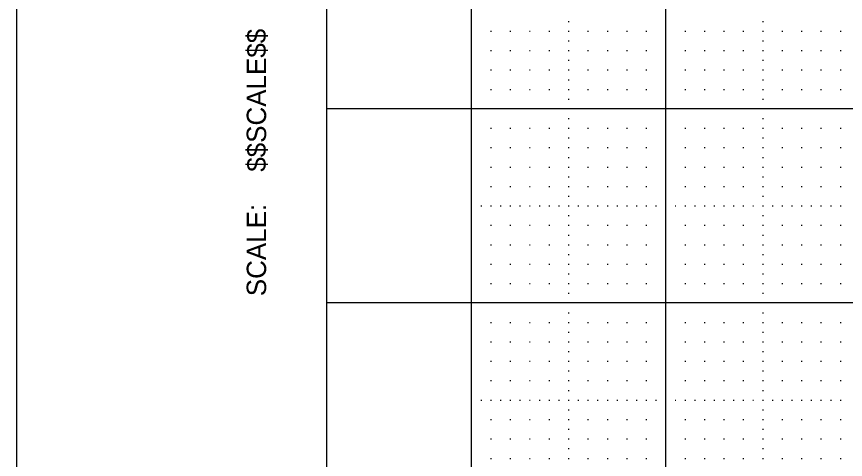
# Model space of a CAD drawing. Extents: x -1.6 to 32.7, y -1.7 to 21.9.
# Drawn here: x -1.598 to 2.67, y 2.487 to 4.768 of the extents above; entities that cross this region are included whole.
import ezdxf

# ---------------------------------------------------------------- set-up
doc = ezdxf.new("R2010")
doc.units = 0
for name, color, linetype in [('Level 1', 7, 'Continuous'), ('Level 5', 7, 'Continuous'), ('Level 63', 7, 'Continuous'), ('R_Border_Dark', 7, 'Continuous')]:
    doc.layers.add(name, color=color, linetype=linetype)

msp = doc.modelspace()

# ---------------------------------------------------------------- linework, layer by layer
at = {"layer": 'Level 1'}
msp.add_line((-0.001, -0.001), (-0.001, 20.545), dxfattribs=at)
msp.add_lwpolyline([(0.745, 10.272), (30.745, 10.272), (30.745, 0.293), (0.745, 0.293)], close=True, dxfattribs=at)
at = {"layer": 'Level 5'}
for p, q in [((1.2425, 4.743), (1.2475, 4.743)), ((2.2425, 4.743), (2.2475, 4.743)), ((0.8425, 4.693), (0.8475, 4.693)), ((0.9425, 4.693), (0.9475, 4.693)), ((1.0425, 4.693), (1.0475, 4.693)), ((1.1425, 4.693), (1.1475, 4.693)), ((1.2425, 4.693), (1.2475, 4.693)), ((1.3425, 4.693), (1.3475, 4.693)), ((1.4425, 4.693), (1.4475, 4.693)), ((1.5425, 4.693), (1.5475, 4.693)), ((1.6425, 4.693), (1.6475, 4.693)), ((1.8425, 4.693), (1.8475, 4.693)), ((1.9425, 4.693), (1.9475, 4.693)), ((2.0425, 4.693), (2.0475, 4.693)), ((2.1425, 4.693), (2.1475, 4.693)), ((2.2425, 4.693), (2.2475, 4.693)), ((2.3425, 4.693), (2.3475, 4.693)), ((2.4425, 4.693), (2.4475, 4.693)), ((2.5425, 4.693), (2.5475, 4.693)), ((2.6425, 4.693), (2.6475, 4.693)), ((1.2425, 4.643), (1.2475, 4.643)), ((2.2425, 4.643), (2.2475, 4.643)), ((0.8425, 4.593), (0.8475, 4.593)), ((0.9425, 4.593), (0.9475, 4.593)), ((1.0425, 4.593), (1.0475, 4.593)), ((1.1425, 4.593), (1.1475, 4.593)), ((1.2425, 4.593), (1.2475, 4.593)), ((1.3425, 4.593), (1.3475, 4.593)), ((1.4425, 4.593), (1.4475, 4.593)), ((1.5425, 4.593), (1.5475, 4.593)), ((1.6425, 4.593), (1.6475, 4.593)), ((1.8425, 4.593), (1.8475, 4.593)), ((1.9425, 4.593), (1.9475, 4.593)), ((2.0425, 4.593), (2.0475, 4.593)), ((2.1425, 4.593), (2.1475, 4.593)), ((2.2425, 4.593), (2.2475, 4.593)), ((2.3425, 4.593), (2.3475, 4.593)), ((2.4425, 4.593), (2.4475, 4.593)), ((2.5425, 4.593), (2.5475, 4.593)), ((2.6425, 4.593), (2.6475, 4.593)), ((1.2425, 4.543), (1.2475, 4.543)), ((2.2425, 4.543), (2.2475, 4.543)), ((0.8425, 4.493), (0.8475, 4.493)), ((0.9425, 4.493), (0.9475, 4.493)), ((1.0425, 4.493), (1.0475, 4.493)), ((1.1425, 4.493), (1.1475, 4.493)), ((1.2425, 4.493), (1.2475, 4.493)), ((1.3425, 4.493), (1.3475, 4.493)), ((1.4425, 4.493), (1.4475, 4.493)), ((1.5425, 4.493), (1.5475, 4.493)), ((1.6425, 4.493), (1.6475, 4.493)), ((1.8425, 4.493), (1.8475, 4.493)), ((1.9425, 4.493), (1.9475, 4.493)), ((2.0425, 4.493), (2.0475, 4.493)), ((2.1425, 4.493), (2.1475, 4.493)), ((2.2425, 4.493), (2.2475, 4.493)), ((2.3425, 4.493), (2.3475, 4.493)), ((2.4425, 4.493), (2.4475, 4.493)), ((2.5425, 4.493), (2.5475, 4.493)), ((2.6425, 4.493), (2.6475, 4.493)), ((1.2425, 4.443), (1.2475, 4.443)), ((2.2425, 4.443), (2.2475, 4.443)), ((0.8425, 4.393), (0.8475, 4.393)), ((0.9425, 4.393), (0.9475, 4.393)), ((1.0425, 4.393), (1.0475, 4.393)), ((1.1425, 4.393), (1.1475, 4.393)), ((1.2425, 4.393), (1.2475, 4.393)), ((1.3425, 4.393), (1.3475, 4.393)), ((1.4425, 4.393), (1.4475, 4.393)), ((1.5425, 4.393), (1.5475, 4.393)), ((1.6425, 4.393), (1.6475, 4.393)), ((1.8425, 4.393), (1.8475, 4.393)), ((1.9425, 4.393), (1.9475, 4.393)), ((2.0425, 4.393), (2.0475, 4.393)), ((2.1425, 4.393), (2.1475, 4.393)), ((2.2425, 4.393), (2.2475, 4.393)), ((2.3425, 4.393), (2.3475, 4.393)), ((2.4425, 4.393), (2.4475, 4.393)), ((2.5425, 4.393), (2.5475, 4.393)), ((2.6425, 4.393), (2.6475, 4.393)), ((1.2425, 4.343), (1.2475, 4.343)), ((2.2425, 4.343), (2.2475, 4.343)), ((1.2425, 4.243), (1.2475, 4.243)), ((2.2425, 4.243), (2.2475, 4.243)), ((0.8425, 4.193), (0.8475, 4.193)), ((0.9425, 4.193), (0.9475, 4.193)), ((1.0425, 4.193), (1.0475, 4.193)), ((1.1425, 4.193), (1.1475, 4.193)), ((1.2425, 4.193), (1.2475, 4.193)), ((1.3425, 4.193), (1.3475, 4.193)), ((1.4425, 4.193), (1.4475, 4.193)), ((1.5425, 4.193), (1.5475, 4.193)), ((1.6425, 4.193), (1.6475, 4.193)), ((1.8425, 4.193), (1.8475, 4.193)), ((1.9425, 4.193), (1.9475, 4.193)), ((2.0425, 4.193), (2.0475, 4.193)), ((2.1425, 4.193), (2.1475, 4.193)), ((2.2425, 4.193), (2.2475, 4.193)), ((2.3425, 4.193), (2.3475, 4.193)), ((2.4425, 4.193), (2.4475, 4.193)), ((2.5425, 4.193), (2.5475, 4.193)), ((2.6425, 4.193), (2.6475, 4.193)), ((1.2425, 4.143), (1.2475, 4.143)), ((2.2425, 4.143), (2.2475, 4.143)), ((0.8425, 4.093), (0.8475, 4.093)), ((0.9425, 4.093), (0.9475, 4.093)), ((1.0425, 4.093), (1.0475, 4.093)), ((1.1425, 4.093), (1.1475, 4.093)), ((1.2425, 4.093), (1.2475, 4.093)), ((1.3425, 4.093), (1.3475, 4.093)), ((1.4425, 4.093), (1.4475, 4.093)), ((1.5425, 4.093), (1.5475, 4.093)), ((1.6425, 4.093), (1.6475, 4.093)), ((1.8425, 4.093), (1.8475, 4.093)), ((1.9425, 4.093), (1.9475, 4.093)), ((2.0425, 4.093), (2.0475, 4.093)), ((2.1425, 4.093), (2.1475, 4.093)), ((2.2425, 4.093), (2.2475, 4.093)), ((2.3425, 4.093), (2.3475, 4.093)), ((2.4425, 4.093), (2.4475, 4.093)), ((2.5425, 4.093), (2.5475, 4.093)), ((2.6425, 4.093), (2.6475, 4.093)), ((1.2425, 4.043), (1.2475, 4.043)), ((2.2425, 4.043), (2.2475, 4.043)), ((0.8425, 3.993), (0.8475, 3.993)), ((0.9425, 3.993), (0.9475, 3.993)), ((1.0425, 3.993), (1.0475, 3.993)), ((1.1425, 3.993), (1.1475, 3.993)), ((1.2425, 3.993), (1.2475, 3.993)), ((1.3425, 3.993), (1.3475, 3.993)), ((1.4425, 3.993), (1.4475, 3.993)), ((1.5425, 3.993), (1.5475, 3.993)), ((1.6425, 3.993), (1.6475, 3.993)), ((1.8425, 3.993), (1.8475, 3.993)), ((1.9425, 3.993), (1.9475, 3.993)), ((2.0425, 3.993), (2.0475, 3.993)), ((2.1425, 3.993), (2.1475, 3.993)), ((2.2425, 3.993), (2.2475, 3.993)), ((2.3425, 3.993), (2.3475, 3.993)), ((2.4425, 3.993), (2.4475, 3.993)), ((2.5425, 3.993), (2.5475, 3.993)), ((2.6425, 3.993), (2.6475, 3.993)), ((1.2425, 3.943), (1.2475, 3.943)), ((2.2425, 3.943), (2.2475, 3.943)), ((0.8425, 3.893), (0.8475, 3.893)), ((0.9425, 3.893), (0.9475, 3.893)), ((1.0425, 3.893), (1.0475, 3.893)), ((1.1425, 3.893), (1.1475, 3.893)), ((1.2425, 3.893), (1.2475, 3.893)), ((1.3425, 3.893), (1.3475, 3.893)), ((1.4425, 3.893), (1.4475, 3.893)), ((1.5425, 3.893), (1.5475, 3.893)), ((1.6425, 3.893), (1.6475, 3.893)), ((1.8425, 3.893), (1.8475, 3.893)), ((1.9425, 3.893), (1.9475, 3.893)), ((2.0425, 3.893), (2.0475, 3.893)), ((2.1425, 3.893), (2.1475, 3.893)), ((2.2425, 3.893), (2.2475, 3.893)), ((2.3425, 3.893), (2.3475, 3.893)), ((2.4425, 3.893), (2.4475, 3.893)), ((2.5425, 3.893), (2.5475, 3.893)), ((2.6425, 3.893), (2.6475, 3.893)), ((1.2425, 3.843), (1.2475, 3.843)), ((2.2425, 3.843), (2.2475, 3.843)), ((0.7925, 3.793), (0.7975, 3.793)), ((0.8425, 3.793), (0.8475, 3.793)), ((0.8925, 3.793), (0.8975, 3.793)), ((0.9425, 3.793), (0.9475, 3.793)), ((0.9925, 3.793), (0.9975, 3.793)), ((1.0425, 3.793), (1.0475, 3.793)), ((1.0925, 3.793), (1.0975, 3.793)), ((1.1425, 3.793), (1.1475, 3.793)), ((1.1925, 3.793), (1.1975, 3.793)), ((1.2425, 3.793), (1.2475, 3.793)), ((1.2925, 3.793), (1.2975, 3.793)), ((1.3425, 3.793), (1.3475, 3.793)), ((1.3925, 3.793), (1.3975, 3.793)), ((1.4425, 3.793), (1.4475, 3.793)), ((1.4925, 3.793), (1.4975, 3.793)), ((1.5425, 3.793), (1.5475, 3.793)), ((1.5925, 3.793), (1.5975, 3.793)), ((1.6425, 3.793), (1.6475, 3.793)), ((1.6925, 3.793), (1.6975, 3.793)), ((1.7925, 3.793), (1.7975, 3.793)), ((1.8425, 3.793), (1.8475, 3.793)), ((1.8925, 3.793), (1.8975, 3.793)), ((1.9425, 3.793), (1.9475, 3.793)), ((1.9925, 3.793), (1.9975, 3.793)), ((2.0425, 3.793), (2.0475, 3.793)), ((2.0925, 3.793), (2.0975, 3.793)), ((2.1425, 3.793), (2.1475, 3.793)), ((2.1925, 3.793), (2.1975, 3.793)), ((2.2425, 3.793), (2.2475, 3.793)), ((2.2925, 3.793), (2.2975, 3.793)), ((2.3425, 3.793), (2.3475, 3.793)), ((2.3925, 3.793), (2.3975, 3.793)), ((2.4425, 3.793), (2.4475, 3.793)), ((2.4925, 3.793), (2.4975, 3.793)), ((2.5425, 3.793), (2.5475, 3.793)), ((2.5925, 3.793), (2.5975, 3.793)), ((2.6425, 3.793), (2.6475, 3.793)), ((1.2425, 3.743), (1.2475, 3.743)), ((2.2425, 3.743), (2.2475, 3.743)), ((0.8425, 3.693), (0.8475, 3.693)), ((0.9425, 3.693), (0.9475, 3.693)), ((1.0425, 3.693), (1.0475, 3.693)), ((1.1425, 3.693), (1.1475, 3.693)), ((1.2425, 3.693), (1.2475, 3.693)), ((1.3425, 3.693), (1.3475, 3.693)), ((1.4425, 3.693), (1.4475, 3.693)), ((1.5425, 3.693), (1.5475, 3.693)), ((1.6425, 3.693), (1.6475, 3.693)), ((1.8425, 3.693), (1.8475, 3.693)), ((1.9425, 3.693), (1.9475, 3.693)), ((2.0425, 3.693), (2.0475, 3.693)), ((2.1425, 3.693), (2.1475, 3.693)), ((2.2425, 3.693), (2.2475, 3.693)), ((2.3425, 3.693), (2.3475, 3.693)), ((2.4425, 3.693), (2.4475, 3.693)), ((2.5425, 3.693), (2.5475, 3.693)), ((2.6425, 3.693), (2.6475, 3.693)), ((1.2425, 3.643), (1.2475, 3.643)), ((2.2425, 3.643), (2.2475, 3.643)), ((0.8425, 3.593), (0.8475, 3.593)), ((0.9425, 3.593), (0.9475, 3.593)), ((1.0425, 3.593), (1.0475, 3.593)), ((1.1425, 3.593), (1.1475, 3.593)), ((1.2425, 3.593), (1.2475, 3.593)), ((1.3425, 3.593), (1.3475, 3.593)), ((1.4425, 3.593), (1.4475, 3.593)), ((1.5425, 3.593), (1.5475, 3.593)), ((1.6425, 3.593), (1.6475, 3.593)), ((1.8425, 3.593), (1.8475, 3.593)), ((1.9425, 3.593), (1.9475, 3.593)), ((2.0425, 3.593), (2.0475, 3.593)), ((2.1425, 3.593), (2.1475, 3.593)), ((2.2425, 3.593), (2.2475, 3.593)), ((2.3425, 3.593), (2.3475, 3.593)), ((2.4425, 3.593), (2.4475, 3.593)), ((2.5425, 3.593), (2.5475, 3.593)), ((2.6425, 3.593), (2.6475, 3.593)), ((1.2425, 3.543), (1.2475, 3.543)), ((2.2425, 3.543), (2.2475, 3.543)), ((0.8425, 3.493), (0.8475, 3.493)), ((0.9425, 3.493), (0.9475, 3.493)), ((1.0425, 3.493), (1.0475, 3.493)), ((1.1425, 3.493), (1.1475, 3.493)), ((1.2425, 3.493), (1.2475, 3.493)), ((1.3425, 3.493), (1.3475, 3.493)), ((1.4425, 3.493), (1.4475, 3.493)), ((1.5425, 3.493), (1.5475, 3.493)), ((1.6425, 3.493), (1.6475, 3.493)), ((1.8425, 3.493), (1.8475, 3.493)), ((1.9425, 3.493), (1.9475, 3.493)), ((2.0425, 3.493), (2.0475, 3.493)), ((2.1425, 3.493), (2.1475, 3.493)), ((2.2425, 3.493), (2.2475, 3.493)), ((2.3425, 3.493), (2.3475, 3.493)), ((2.4425, 3.493), (2.4475, 3.493)), ((2.5425, 3.493), (2.5475, 3.493)), ((2.6425, 3.493), (2.6475, 3.493)), ((1.2425, 3.443), (1.2475, 3.443)), ((2.2425, 3.443), (2.2475, 3.443)), ((0.8425, 3.393), (0.8475, 3.393)), ((0.9425, 3.393), (0.9475, 3.393)), ((1.0425, 3.393), (1.0475, 3.393)), ((1.1425, 3.393), (1.1475, 3.393)), ((1.2425, 3.393), (1.2475, 3.393)), ((1.3425, 3.393), (1.3475, 3.393)), ((1.4425, 3.393), (1.4475, 3.393)), ((1.5425, 3.393), (1.5475, 3.393)), ((1.6425, 3.393), (1.6475, 3.393)), ((1.8425, 3.393), (1.8475, 3.393)), ((1.9425, 3.393), (1.9475, 3.393)), ((2.0425, 3.393), (2.0475, 3.393)), ((2.1425, 3.393), (2.1475, 3.393)), ((2.2425, 3.393), (2.2475, 3.393)), ((2.3425, 3.393), (2.3475, 3.393)), ((2.4425, 3.393), (2.4475, 3.393)), ((2.5425, 3.393), (2.5475, 3.393)), ((2.6425, 3.393), (2.6475, 3.393)), ((1.2425, 3.343), (1.2475, 3.343)), ((2.2425, 3.343), (2.2475, 3.343)), ((1.2425, 3.243), (1.2475, 3.243)), ((2.2425, 3.243), (2.2475, 3.243)), ((0.8425, 3.193), (0.8475, 3.193)), ((0.9425, 3.193), (0.9475, 3.193)), ((1.0425, 3.193), (1.0475, 3.193)), ((1.1425, 3.193), (1.1475, 3.193)), ((1.2425, 3.193), (1.2475, 3.193)), ((1.3425, 3.193), (1.3475, 3.193)), ((1.4425, 3.193), (1.4475, 3.193)), ((1.5425, 3.193), (1.5475, 3.193)), ((1.6425, 3.193), (1.6475, 3.193)), ((1.8425, 3.193), (1.8475, 3.193)), ((1.9425, 3.193), (1.9475, 3.193)), ((2.0425, 3.193), (2.0475, 3.193)), ((2.1425, 3.193), (2.1475, 3.193)), ((2.2425, 3.193), (2.2475, 3.193)), ((2.3425, 3.193), (2.3475, 3.193)), ((2.4425, 3.193), (2.4475, 3.193)), ((2.5425, 3.193), (2.5475, 3.193)), ((2.6425, 3.193), (2.6475, 3.193)), ((1.2425, 3.143), (1.2475, 3.143)), ((2.2425, 3.143), (2.2475, 3.143)), ((0.8425, 3.093), (0.8475, 3.093)), ((0.9425, 3.093), (0.9475, 3.093)), ((1.0425, 3.093), (1.0475, 3.093)), ((1.1425, 3.093), (1.1475, 3.093)), ((1.2425, 3.093), (1.2475, 3.093)), ((1.3425, 3.093), (1.3475, 3.093)), ((1.4425, 3.093), (1.4475, 3.093)), ((1.5425, 3.093), (1.5475, 3.093)), ((1.6425, 3.093), (1.6475, 3.093)), ((1.8425, 3.093), (1.8475, 3.093)), ((1.9425, 3.093), (1.9475, 3.093)), ((2.0425, 3.093), (2.0475, 3.093)), ((2.1425, 3.093), (2.1475, 3.093)), ((2.2425, 3.093), (2.2475, 3.093)), ((2.3425, 3.093), (2.3475, 3.093)), ((2.4425, 3.093), (2.4475, 3.093)), ((2.5425, 3.093), (2.5475, 3.093)), ((2.6425, 3.093), (2.6475, 3.093)), ((1.2425, 3.043), (1.2475, 3.043)), ((2.2425, 3.043), (2.2475, 3.043)), ((0.8425, 2.993), (0.8475, 2.993)), ((0.9425, 2.993), (0.9475, 2.993)), ((1.0425, 2.993), (1.0475, 2.993)), ((1.1425, 2.993), (1.1475, 2.993)), ((1.2425, 2.993), (1.2475, 2.993)), ((1.3425, 2.993), (1.3475, 2.993)), ((1.4425, 2.993), (1.4475, 2.993)), ((1.5425, 2.993), (1.5475, 2.993)), ((1.6425, 2.993), (1.6475, 2.993)), ((1.8425, 2.993), (1.8475, 2.993)), ((1.9425, 2.993), (1.9475, 2.993)), ((2.0425, 2.993), (2.0475, 2.993)), ((2.1425, 2.993), (2.1475, 2.993)), ((2.2425, 2.993), (2.2475, 2.993)), ((2.3425, 2.993), (2.3475, 2.993)), ((2.4425, 2.993), (2.4475, 2.993)), ((2.5425, 2.993), (2.5475, 2.993)), ((2.6425, 2.993), (2.6475, 2.993)), ((1.2425, 2.943), (1.2475, 2.943)), ((2.2425, 2.943), (2.2475, 2.943)), ((0.8425, 2.893), (0.8475, 2.893)), ((0.9425, 2.893), (0.9475, 2.893)), ((1.0425, 2.893), (1.0475, 2.893)), ((1.1425, 2.893), (1.1475, 2.893)), ((1.2425, 2.893), (1.2475, 2.893)), ((1.3425, 2.893), (1.3475, 2.893)), ((1.4425, 2.893), (1.4475, 2.893)), ((1.5425, 2.893), (1.5475, 2.893)), ((1.6425, 2.893), (1.6475, 2.893)), ((1.8425, 2.893), (1.8475, 2.893)), ((1.9425, 2.893), (1.9475, 2.893)), ((2.0425, 2.893), (2.0475, 2.893)), ((2.1425, 2.893), (2.1475, 2.893)), ((2.2425, 2.893), (2.2475, 2.893)), ((2.3425, 2.893), (2.3475, 2.893)), ((2.4425, 2.893), (2.4475, 2.893)), ((2.5425, 2.893), (2.5475, 2.893)), ((2.6425, 2.893), (2.6475, 2.893)), ((1.2425, 2.843), (1.2475, 2.843)), ((2.2425, 2.843), (2.2475, 2.843)), ((0.7925, 2.793), (0.7975, 2.793)), ((0.8425, 2.793), (0.8475, 2.793)), ((0.8925, 2.793), (0.8975, 2.793)), ((0.9425, 2.793), (0.9475, 2.793)), ((0.9925, 2.793), (0.9975, 2.793)), ((1.0425, 2.793), (1.0475, 2.793)), ((1.0925, 2.793), (1.0975, 2.793)), ((1.1425, 2.793), (1.1475, 2.793)), ((1.1925, 2.793), (1.1975, 2.793)), ((1.2425, 2.793), (1.2475, 2.793)), ((1.2925, 2.793), (1.2975, 2.793)), ((1.3425, 2.793), (1.3475, 2.793)), ((1.3925, 2.793), (1.3975, 2.793)), ((1.4425, 2.793), (1.4475, 2.793)), ((1.4925, 2.793), (1.4975, 2.793)), ((1.5425, 2.793), (1.5475, 2.793)), ((1.5925, 2.793), (1.5975, 2.793)), ((1.6425, 2.793), (1.6475, 2.793)), ((1.6925, 2.793), (1.6975, 2.793)), ((1.7925, 2.793), (1.7975, 2.793)), ((1.8425, 2.793), (1.8475, 2.793)), ((1.8925, 2.793), (1.8975, 2.793)), ((1.9425, 2.793), (1.9475, 2.793)), ((1.9925, 2.793), (1.9975, 2.793)), ((2.0425, 2.793), (2.0475, 2.793)), ((2.0925, 2.793), (2.0975, 2.793)), ((2.1425, 2.793), (2.1475, 2.793)), ((2.1925, 2.793), (2.1975, 2.793)), ((2.2425, 2.793), (2.2475, 2.793)), ((2.2925, 2.793), (2.2975, 2.793)), ((2.3425, 2.793), (2.3475, 2.793)), ((2.3925, 2.793), (2.3975, 2.793)), ((2.4425, 2.793), (2.4475, 2.793)), ((2.4925, 2.793), (2.4975, 2.793)), ((2.5425, 2.793), (2.5475, 2.793)), ((2.5925, 2.793), (2.5975, 2.793)), ((2.6425, 2.793), (2.6475, 2.793)), ((1.2425, 2.743), (1.2475, 2.743)), ((2.2425, 2.743), (2.2475, 2.743)), ((0.8425, 2.693), (0.8475, 2.693)), ((0.9425, 2.693), (0.9475, 2.693)), ((1.0425, 2.693), (1.0475, 2.693)), ((1.1425, 2.693), (1.1475, 2.693)), ((1.2425, 2.693), (1.2475, 2.693)), ((1.3425, 2.693), (1.3475, 2.693)), ((1.4425, 2.693), (1.4475, 2.693)), ((1.5425, 2.693), (1.5475, 2.693)), ((1.6425, 2.693), (1.6475, 2.693)), ((1.8425, 2.693), (1.8475, 2.693)), ((1.9425, 2.693), (1.9475, 2.693)), ((2.0425, 2.693), (2.0475, 2.693)), ((2.1425, 2.693), (2.1475, 2.693)), ((2.2425, 2.693), (2.2475, 2.693)), ((2.3425, 2.693), (2.3475, 2.693)), ((2.4425, 2.693), (2.4475, 2.693)), ((2.5425, 2.693), (2.5475, 2.693)), ((2.6425, 2.693), (2.6475, 2.693)), ((1.2425, 2.643), (1.2475, 2.643)), ((2.2425, 2.643), (2.2475, 2.643)), ((0.8425, 2.593), (0.8475, 2.593)), ((0.9425, 2.593), (0.9475, 2.593)), ((1.0425, 2.593), (1.0475, 2.593)), ((1.1425, 2.593), (1.1475, 2.593)), ((1.2425, 2.593), (1.2475, 2.593)), ((1.3425, 2.593), (1.3475, 2.593)), ((1.4425, 2.593), (1.4475, 2.593)), ((1.5425, 2.593), (1.5475, 2.593)), ((1.6425, 2.593), (1.6475, 2.593)), ((1.8425, 2.593), (1.8475, 2.593)), ((1.9425, 2.593), (1.9475, 2.593)), ((2.0425, 2.593), (2.0475, 2.593)), ((2.1425, 2.593), (2.1475, 2.593)), ((2.2425, 2.593), (2.2475, 2.593)), ((2.3425, 2.593), (2.3475, 2.593)), ((2.4425, 2.593), (2.4475, 2.593)), ((2.5425, 2.593), (2.5475, 2.593)), ((2.6425, 2.593), (2.6475, 2.593)), ((1.2425, 2.543), (1.2475, 2.543)), ((2.2425, 2.543), (2.2475, 2.543)), ((0.8425, 2.493), (0.8475, 2.493)), ((0.9425, 2.493), (0.9475, 2.493)), ((1.0425, 2.493), (1.0475, 2.493)), ((1.1425, 2.493), (1.1475, 2.493)), ((1.2425, 2.493), (1.2475, 2.493)), ((1.3425, 2.493), (1.3475, 2.493)), ((1.4425, 2.493), (1.4475, 2.493)), ((1.5425, 2.493), (1.5475, 2.493)), ((1.6425, 2.493), (1.6475, 2.493)), ((1.8425, 2.493), (1.8475, 2.493)), ((1.9425, 2.493), (1.9475, 2.493)), ((2.0425, 2.493), (2.0475, 2.493)), ((2.1425, 2.493), (2.1475, 2.493)), ((2.2425, 2.493), (2.2475, 2.493)), ((2.3425, 2.493), (2.3475, 2.493)), ((2.4425, 2.493), (2.4475, 2.493)), ((2.5425, 2.493), (2.5475, 2.493)), ((2.6425, 2.493), (2.6475, 2.493))]:
    msp.add_line(p, q, dxfattribs=at)
at = {"layer": 'Level 63'}
msp.add_lwpolyline([(-1.598, -0.727), (32.402, -0.727), (32.402, 21.273), (-1.598, 21.273)], close=True, dxfattribs=at)
msp.add_lwpolyline([(30.745, 8.293), (30.745, 0.293), (0.745, 0.293), (0.745, 8.293)], dxfattribs=at)
at = {"layer": 'R_Border_Dark'}
for p, q in [((0.745, 0.293), (0.745, 8.293)), ((1.745, 0.293), (1.745, 8.293)), ((31.617, 4.293), (-0.001, 4.293)), ((31.617, 3.293), (-0.001, 3.293))]:
    msp.add_line(p, q, dxfattribs=at)
msp.add_lwpolyline([(30.745, 8.293), (30.745, 0.293), (0.745, 0.293), (0.745, 8.293)], dxfattribs=at)

# ---------------------------------------------------------------- texts
at = {"layer": 'Level 1'}
for s, p in [('$$SCALE$$', (-0.313, 3.969)), ('SCALE:', (-0.313, 3.328))]:
    msp.add_text(s, height=0.1, rotation=90, dxfattribs=at).set_placement(p)

doc.saveas('drawing.dxf')
